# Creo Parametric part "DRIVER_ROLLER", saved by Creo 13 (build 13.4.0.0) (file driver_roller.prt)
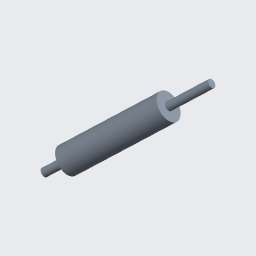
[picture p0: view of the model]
Units: millimeter Newton Second (mmNs); MM, TONNE, SECS

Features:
  1. datum plane "RIGHT"
  2. datum plane "TOP"
  3. datum plane "FRONT"
  4. coordinate system
  5. protrusion
  6. protrusion
  7. protrusion
  8. datum axis

Surfaces: 4 plane, 3 cylinder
